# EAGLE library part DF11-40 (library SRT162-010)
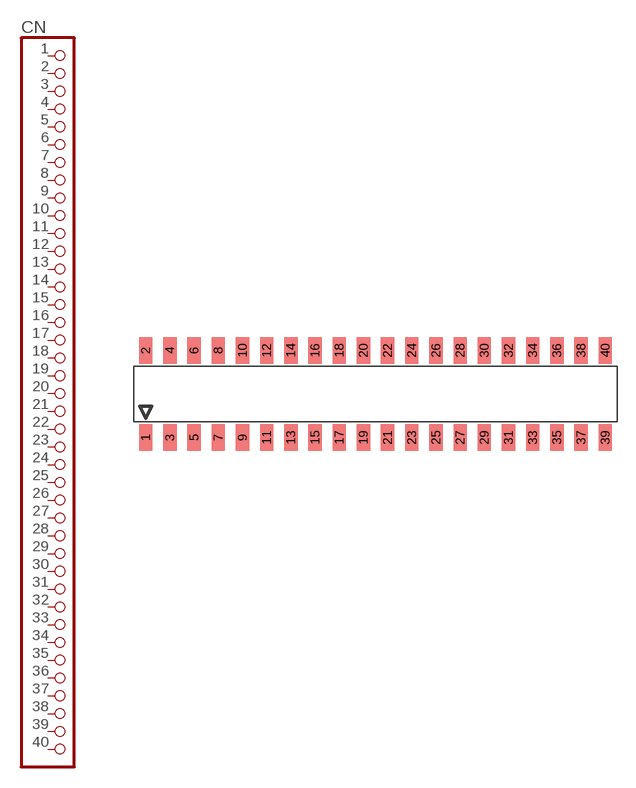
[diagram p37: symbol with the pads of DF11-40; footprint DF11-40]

Designator prefix CN

## DF11-40  [DF11-40]
1  1  pas
2  2  pas
3  3  pas
4  4  pas
5  5  pas
6  6  pas
7  7  pas
8  8  pas
9  9  pas
10  10  pas
11  11  pas
12  12  pas
13  13  pas
14  14  pas
15  15  pas
16  16  pas
17  17  pas
18  18  pas
19  19  pas
20  20  pas
21  21  pas
22  22  pas
23  23  pas
24  24  pas
25  25  pas
26  26  pas
27  27  pas
28  28  pas
29  29  pas
30  30  pas
31  31  pas
32  32  pas
33  33  pas
34  34  pas
35  35  pas
36  36  pas
37  37  pas
38  38  pas
39  39  pas
40  40  pas

## Footprint DF11-40 (pad centres in mm)
smd 1.1 x 2.2: 1 -20,-3.6; 2 -20,3.6; 3 -18,-3.6; 4 -18,3.6; 5 -16,-3.6; 6 -16,3.6; 7 -14,-3.6; 8 -14,3.6; 9 -12,-3.6; 10 -12,3.6; 11 -10,-3.6; 12 -10,3.6; 13 -8,-3.6; 14 -8,3.6; 15 -6,-3.6; 16 -6,3.6; 17 -4,-3.6; 18 -4,3.6; 19 -2,-3.6; 20 -2,3.6; 21 0,-3.6; 22 0,3.6; 23 2,-3.6; 24 2,3.6; 25 4,-3.6; 26 4,3.6; 27 6,-3.6; 28 6,3.6; 29 8,-3.6; 30 8,3.6; 31 10,-3.6; 32 10,3.6; 33 12,-3.6; 34 12,3.6; 35 14,-3.6; 36 14,3.6; 37 16,-3.6; 38 16,3.6; 39 18,-3.6; 40 18,3.6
